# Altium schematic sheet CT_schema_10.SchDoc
size 274 x 160 mm
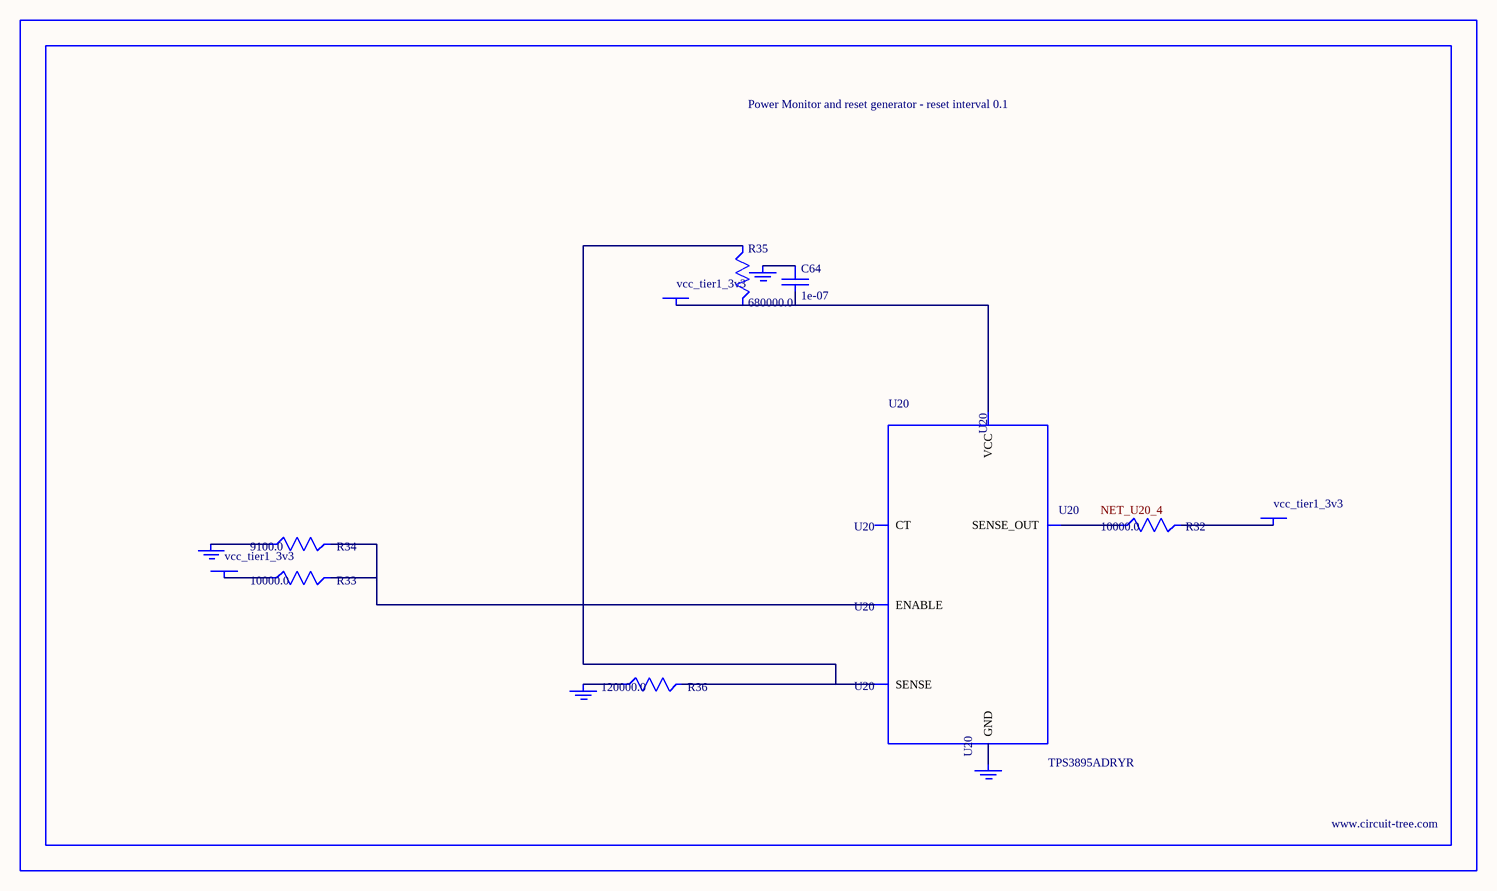
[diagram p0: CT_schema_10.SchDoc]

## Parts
BORDER9  (no value)
C64  1e-07  [C0402]
GND_INSTANCE_9_0  (no value)
GND_INSTANCE_9_1  (no value)
GND_INSTANCE_9_2  (no value)
GND_INSTANCE_9_3  (no value)
POWER_INSTANCE_9_0  vcc_tier1_3v3
POWER_INSTANCE_9_1  vcc_tier1_3v3
POWER_INSTANCE_9_2  vcc_tier1_3v3
R32  10000.0  [R0603]
R33  10000.0  [R0603]
R34  9100.0  [R0603]
R35  680000.0  [R0603]
R36  120000.0  [R0603]
U20  TPS3895ADRYR  [SON-6]

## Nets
NetC64_1: C64.1 GND_INSTANCE_9_2.0(GND)
NetC64_2: C64.2 POWER_INSTANCE_9_2.0(PWR) R35.2 U20.6(VCC)
NetGND_INSTANCE_9_0_0: GND_INSTANCE_9_0.0(GND) R34.1
NetGND_INSTANCE_9_1_0: GND_INSTANCE_9_1.0(GND) R36.1
NetGND_INSTANCE_9_3_0: GND_INSTANCE_9_3.0(GND) U20.2(GND)
NetPOWER_INSTANCE_9_0_0: POWER_INSTANCE_9_0.0(PWR) R33.1
NetPOWER_INSTANCE_9_1_0: POWER_INSTANCE_9_1.0(PWR) R32.2
NetR32_1: R32.1 U20.4(SENSE_OUT)
NetR33_2: R33.2 R34.2 U20.1(ENABLE)
NetR35_1: R35.1 R36.2 U20.3(SENSE)

Not connected (* = marked no-connect by the designer): U20 5(CT)

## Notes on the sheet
- Labels drawn without touching a wire or pin: NET_U20_4

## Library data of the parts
BORDER9 = BORDER_PAGE9
C64 = C0402C104K3RACTU
GND_INSTANCE_9_0-GND_INSTANCE_9_3 = GND
POWER_INSTANCE_9_0-POWER_INSTANCE_9_2 = PWR
R32 R33 = RC0603JR-0710KL
R34 = RC0603JR-079K1L
R35 = RC0603JR-07680KL
R36 = RC0603JR-07120KL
